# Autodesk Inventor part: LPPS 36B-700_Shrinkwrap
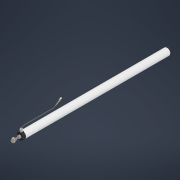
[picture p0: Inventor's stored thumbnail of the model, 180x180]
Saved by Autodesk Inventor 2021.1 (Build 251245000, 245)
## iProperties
Created: 2020-09
Part Number: LPPS 36B-700_Shrinkwrap
Material: Generic
Document SubType Name: Modeling
Designer: J. Nielson
Density: 1 g/cm^3
Appearance: Default
Author: J. Nielson
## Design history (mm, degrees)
derived "LPPS 36B-700.iam"
body "Solid1"
node "LPPS 36B Cable End Cap.iam:1::LPPS-36B PLASTIC CABLE END.ipt"
node "LPPS 36B Cable End Cap.iam:1::LPPS 36B- Cable Gland.ipt:1"
body "Solid2"
node "LPPS 36B Cable End Cap.iam:1::Cable Gland Cap.ipt:1"
body "Solid3"
node "LPPS 36B Cable End Cap.iam:1::Cable.ipt:1"
body "Solid4"
node "LPPS 36B Cable End Cap.iam:1::Cable Gland Seal 1 of 2.ipt:1"
body "Solid5"
node "LPPS 36B Cable End Cap.iam:1::Cable Gland 2 of 2.ipt:1"
body "Solid6"
node "LPPS 36B Cable End Cap.iam:1::#6 Terminal Ring 22 - 18 AWG.i"
body "Solid7"
node "LPPS-36B-700 METAL HOUSING.ipt:1"
body "Solid8"
node "MALE Rod Eye SW.ipt:1"
body "Solid9"
node "LPPS-36B PLASTIC STROKE END.ipt:1"
body "Solid10"
node "LPPS-36B-700 Back Stop.ipt:1"
body "Solid11"
node "LPPS-36B-700 Front Stop.ipt:1"
body "Solid12"
node "AS 1427 - M3 x 16.ipt:1"
body "Solid13"
node "AS 1427 - M3 x 16.ipt:2"
body "Solid14"
node "AS 1427 - M3 x 16.ipt:3"
body "Solid15"
node "AS 1427 - M3 x 16.ipt:4"
body "Solid16"
node "AS 1112 - M8  Type 5.ipt:1"
body "Solid17"
node "AS 1237 - 8.ipt:1"
body "Solid18"
node "AS 1968 - 1976 - 8.ipt:1"
body "Solid19"
